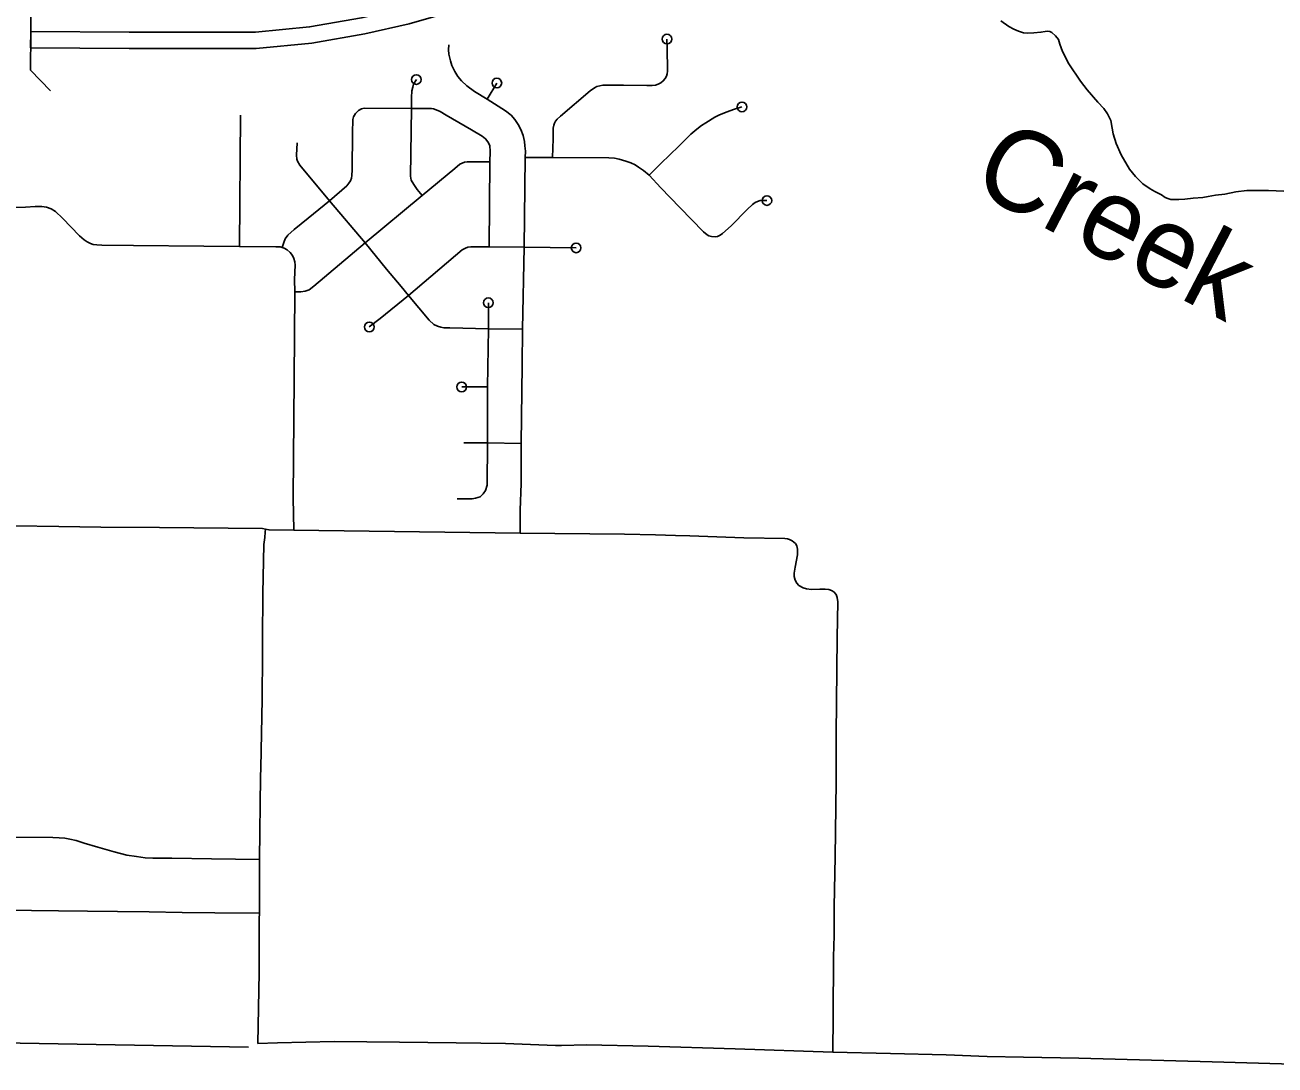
# Model space of a CAD drawing. Extents: x 670147 to 673275, y 705573 to 707613.
# Drawn here: x 671348.9 to 671478.7, y 706020.4 to 706128.4 of the extents above; entities that cross this region are included whole.
import ezdxf

# ---------------------------------------------------------------- set-up
doc = ezdxf.new("R2010")
doc.units = 0
for name, color, linetype in [('10', 7, 'Continuous'), ('2', 7, 'Continuous'), ('33', 7, 'Continuous'), ('34', 7, 'Continuous'), ('35', 7, 'Continuous'), ('39', 7, 'Continuous'), ('6', 7, 'Continuous')]:
    doc.layers.add(name, color=color, linetype=linetype)

msp = doc.modelspace()

# ---------------------------------------------------------------- linework, layer by layer
at = {"layer": '10'}
for points in [[(671431.65, 706153.97), (671430.6, 706155.28), (671422.59, 706148.88), (671415.95, 706143.47), (671412.2, 706140.79), (671407.79, 706137.98), (671403.85, 706135.95), (671399.39, 706133.87), (671393.5, 706131.61), (671388.41, 706130.14), (671383.89, 706129.13), (671378.49, 706128.18), (671372.87, 706127.64), (671359.76, 706127.63), (671349.56, 706127.7), (671349.51, 706126.02)], [(671349.51, 706126.02), (671359.76, 706125.95), (671372.95, 706125.96), (671378.71, 706126.51), (671384.22, 706127.48), (671388.83, 706128.51), (671394.04, 706130.01), (671400.05, 706132.32), (671404.59, 706134.44), (671408.63, 706136.52), (671413.14, 706139.39), (671416.97, 706142.13), (671423.65, 706147.57), (671431.65, 706153.97)]]:
    msp.add_lwpolyline(points, dxfattribs=at)
at = {"layer": '2'}
msp.add_lwpolyline([(671372.15, 706022.28), (671346.48, 706022.71), (671304.46, 706023.34), (671302.39, 706023.6)], dxfattribs=at)
at = {"layer": '33'}
for points in [[(671415.64, 706126.06), (671415.6, 706126.92)], [(671400.35, 706075.64), (671400.35, 706078.01), (671400.45, 706080.79), (671400.45, 706084.95), (671400.58, 706093.07), (671400.61, 706096.81), (671400.77, 706105.33), (671400.88, 706114.64), (671400.9, 706115.3), (671400.86, 706115.85), (671400.81, 706116.3), (671400.68, 706116.92), (671400.43, 706117.52), (671400.15, 706118.05), (671399.81, 706118.56), (671399.41, 706119.01), (671398.85, 706119.49), (671398.07, 706119.97), (671396.94, 706120.7), (671395.63, 706121.48), (671394.81, 706122.07), (671394.25, 706122.59), (671393.89, 706123.05), (671393.57, 706123.56), (671393.26, 706124.17), (671393.12, 706124.65), (671392.95, 706125.34), (671392.91, 706125.79), (671392.95, 706126.32)], [(671403.73, 706114.62), (671403.78, 706116.57), (671403.8, 706117.67), (671403.84, 706117.97), (671403.93, 706118.19), (671404.03, 706118.39), (671404.21, 706118.61), (671404.54, 706118.92), (671407.62, 706121.54), (671408.09, 706121.87), (671408.33, 706121.99), (671408.63, 706122.06), (671408.95, 706122.14), (671409.57, 706122.15), (671411.08, 706122.14), (671413.52, 706122.1), (671414.07, 706122.1), (671414.42, 706122.14), (671414.7, 706122.23), (671414.97, 706122.38), (671415.22, 706122.58), (671415.42, 706122.84), (671415.54, 706123.08), (671415.64, 706123.33), (671415.65, 706123.6), (671415.64, 706126.06), (671415.63, 706126.11)], [(671389.06, 706119.72), (671389.07, 706120.85), (671389.1, 706121.54), (671389.2, 706121.92), (671389.29, 706122.23), (671389.58, 706122.72)], [(671396.94, 706120.7), (671397.94, 706122.36)], [(671413.77, 706112.78), (671414.95, 706113.99), (671416.84, 706115.79), (671418.09, 706117.04), (671418.72, 706117.57), (671419.19, 706117.95), (671419.65, 706118.24), (671420.56, 706118.82), (671421.07, 706119.07), (671421.86, 706119.37), (671422.51, 706119.61), (671423.39, 706119.88)], [(671371.32, 706119.02), (671371.23, 706105.38)], [(671380.57, 706110.13), (671382.37, 706111.7), (671382.58, 706111.96), (671382.74, 706112.2), (671382.84, 706112.49), (671382.89, 706112.76), (671382.93, 706113.34), (671382.94, 706117.18), (671382.99, 706118.56), (671383.04, 706118.85), (671383.25, 706119.2), (671383.56, 706119.51), (671383.89, 706119.69), (671384.17, 706119.76), (671389.06, 706119.72), (671391.15, 706119.73), (671391.36, 706119.69), (671391.64, 706119.59), (671392.05, 706119.41), (671392.67, 706119.04), (671395.32, 706117.5), (671396.4, 706116.85), (671396.77, 706116.58), (671397, 706116.27), (671397.2, 706115.88), (671397.25, 706115.26), (671397.22, 706114.19), (671397.15, 706105.37)], [(671389.06, 706119.72), (671388.98, 706112.69), (671389.05, 706112.27), (671389.31, 706111.82), (671389.67, 706111.31), (671390.19, 706110.69)], [(671377.2, 706116.15), (671377.15, 706114.86), (671377.16, 706114.45), (671377.22, 706114.24), (671377.48, 706113.82), (671380.57, 706110.13), (671384.26, 706105.78), (671386.47, 706103.03), (671388.01, 706101.23), (671388.77, 706100.32), (671390.92, 706097.73), (671391.39, 706097.31), (671391.77, 706097.11), (671392.11, 706097), (671392.44, 706096.94), (671393.06, 706096.93), (671397.07, 706096.84), (671400.61, 706096.81)], [(671376.95, 706100.69), (671377.57, 706100.69), (671378.03, 706100.75), (671378.44, 706100.89), (671378.95, 706101.27), (671384.26, 706105.78), (671390.19, 706110.69), (671393.56, 706113.5), (671394.1, 706113.93), (671394.57, 706114.14), (671394.85, 706114.18), (671395.38, 706114.17), (671397.22, 706114.19)], [(671400.88, 706114.64), (671403.73, 706114.62), (671409.56, 706114.6), (671410.16, 706114.56), (671410.63, 706114.47), (671411.34, 706114.25), (671411.84, 706114.09), (671412.3, 706113.86), (671412.66, 706113.64), (671413.15, 706113.29), (671413.77, 706112.78), (671414.96, 706111.47), (671416.93, 706109.44), (671419.39, 706106.93), (671419.77, 706106.6), (671419.96, 706106.51), (671420.24, 706106.44), (671420.59, 706106.41), (671420.85, 706106.44), (671421.11, 706106.56), (671421.36, 706106.74), (671422.27, 706107.53), (671423.92, 706109.23), (671424.5, 706109.76), (671424.75, 706109.95), (671425.01, 706110.07), (671425.28, 706110.16), (671425.98, 706110.16)], [(671347.74, 706109.45), (671348.99, 706109.49), (671349.98, 706109.54), (671350.69, 706109.53), (671351.17, 706109.47), (671351.67, 706109.3), (671352.11, 706109.03), (671352.84, 706108.34), (671354.61, 706106.51), (671355.08, 706106.08), (671355.4, 706105.86), (671355.74, 706105.7), (671356.03, 706105.6), (671356.39, 706105.55), (671356.93, 706105.53), (671360.22, 706105.51), (671367.5, 706105.43), (671371.23, 706105.38)], [(671380.57, 706110.13), (671378.33, 706108.32), (671376.89, 706107.15), (671376.24, 706106.58), (671375.96, 706106.2), (671375.81, 706105.82), (671375.64, 706105.3)], [(671371.23, 706105.38), (671375, 706105.37), (671375.43, 706105.35), (671375.64, 706105.3), (671375.87, 706105.2), (671376.16, 706105.04), (671376.48, 706104.76), (671376.72, 706104.45), (671376.85, 706104.16), (671376.97, 706103.81), (671377, 706103.44), (671376.94, 706101.97), (671376.95, 706100.69), (671376.88, 706091.66), (671376.78, 706079.3), (671376.84, 706075.96)], [(671400.77, 706105.33), (671397.15, 706105.37), (671395.24, 706105.35), (671394.94, 706105.31), (671394.68, 706105.21), (671394.35, 706105.03), (671388.77, 706100.32)], [(671400.77, 706105.33), (671406.17, 706105.25)], [(671388.77, 706100.32), (671385.82, 706097.93)], [(671397.06, 706099.55), (671397.07, 706096.84)], [(671385.82, 706097.93), (671384.69, 706097.04)], [(671397.07, 706096.84), (671396.97, 706090.81), (671396.95, 706085), (671396.92, 706080.61), (671396.76, 706080.06), (671396.52, 706079.7), (671396.19, 706079.42), (671395.73, 706079.25), (671395.36, 706079.18), (671395, 706079.18), (671393.83, 706079.2)], [(671396.97, 706090.81), (671394.29, 706090.81)], [(671394.52, 706085.01), (671396.95, 706085), (671400.45, 706084.95)], [(671320.96, 706076.28), (671323.77, 706076.29), (671326.32, 706076.33), (671328.49, 706076.35), (671332.84, 706076.37), (671334.88, 706076.37), (671337.83, 706076.35), (671339.69, 706076.37), (671340.67, 706076.39), (671343.41, 706076.46), (671346.22, 706076.42), (671347.93, 706076.4), (671352.44, 706076.34), (671356.83, 706076.26), (671362.91, 706076.22), (671373.61, 706076.11)], [(671400.35, 706075.64), (671376.84, 706075.96), (671374.28, 706075.97), (671373.91, 706076.06), (671373.61, 706076.11)], [(671373.91, 706076.06), (671373.87, 706075.72), (671373.83, 706075.19), (671373.74, 706074.47), (671373.65, 706069.36), (671373.61, 706064.61)], [(671432.82, 706021.77), (671432.86, 706025.45), (671432.89, 706031.66), (671432.96, 706033.87), (671432.96, 706036.87), (671433.06, 706042.02), (671433.18, 706049.82), (671433.17, 706054.72), (671433.26, 706064.8), (671433.33, 706068.49), (671433.28, 706068.94), (671433.18, 706069.27), (671432.94, 706069.53), (671432.69, 706069.69), (671432.42, 706069.78), (671432.02, 706069.81), (671431.47, 706069.83), (671430.6, 706069.79), (671430.1, 706069.84), (671429.76, 706069.94), (671429.31, 706070.21), (671429.08, 706070.45), (671428.93, 706070.75), (671428.81, 706071.12), (671428.81, 706071.47), (671428.93, 706072.1), (671429.16, 706073.39), (671429.16, 706073.96), (671429.08, 706074.3), (671428.94, 706074.55), (671428.62, 706074.82), (671428.34, 706074.97), (671428.11, 706075.05), (671427.84, 706075.08), (671423.58, 706075.13), (671417.97, 706075.36), (671416.49, 706075.4), (671414.4, 706075.45), (671411.2, 706075.52), (671400.35, 706075.64)], [(671373.61, 706064.61), (671373.6, 706063.02), (671373.58, 706058.39), (671373.43, 706051.27), (671373.4, 706050.33), (671373.3, 706041.76), (671373.25, 706030.02), (671373.13, 706022.66)], [(671373.3, 706041.76), (671368.31, 706041.82), (671364.18, 706041.89), (671362.2, 706041.89), (671361.41, 706041.93), (671360.53, 706042.06), (671359.53, 706042.21), (671358.19, 706042.54), (671356.49, 706043.05), (671355.1, 706043.45), (671354.25, 706043.72), (671353.58, 706043.86), (671353.09, 706043.96), (671352.5, 706044.02), (671351.82, 706044.04), (671347.37, 706044.08)]]:
    msp.add_lwpolyline(points, dxfattribs=at)
for centre in [(671415.6, 706126.92), (671389.58, 706122.72), (671397.94, 706122.36), (671423.39, 706119.88), (671425.98, 706110.16), (671406.17, 706105.25), (671397.06, 706099.55), (671384.69, 706097.04), (671394.29, 706090.81)]:
    msp.add_circle(centre, 0.5, dxfattribs=at)
at = {"layer": '34'}
for points in [[(671432.82, 706021.77), (671422.67, 706022.11), (671413.65, 706022.39), (671407.24, 706022.5), (671404.64, 706022.46), (671404.03, 706022.46), (671398.84, 706022.64), (671393.7, 706022.71), (671387.83, 706022.79), (671381.06, 706022.86), (671375.15, 706022.73), (671373.13, 706022.66)], [(671432.82, 706021.77), (671438.82, 706021.61), (671444.58, 706021.49), (671448.84, 706021.32), (671452.62, 706021.22), (671458.38, 706021.12), (671472.21, 706020.75), (671479.41, 706020.56), (671485.51, 706020.42)]]:
    msp.add_lwpolyline(points, dxfattribs=at)
at = {"layer": '35'}
for points in [[(671450.28, 706128.83), (671451.11, 706128.23), (671451.61, 706127.94), (671452.11, 706127.73), (671452.61, 706127.57), (671453.04, 706127.54), (671453.71, 706127.57), (671454.44, 706127.64), (671454.88, 706127.72), (671455.15, 706127.73), (671455.36, 706127.72), (671455.56, 706127.62), (671455.96, 706127.27), (671456.27, 706126.87), (671456.39, 706126.4), (671456.68, 706125.65), (671457.33, 706124.35), (671458.53, 706122.56), (671459.23, 706121.65), (671460.33, 706120.39), (671460.98, 706119.72), (671461.35, 706119.17), (671461.68, 706118.47), (671461.82, 706117.66), (671461.95, 706117.08), (671462.26, 706116.08), (671462.76, 706114.92), (671463.63, 706113.43), (671464.27, 706112.66)], [(671464.27, 706112.66), (671465, 706111.89), (671465.77, 706111.36), (671466.27, 706111.11), (671466.95, 706110.76), (671467.33, 706110.49), (671467.62, 706110.36), (671467.93, 706110.28), (671468.3, 706110.28), (671468.74, 706110.26), (671469.38, 706110.3), (671470.23, 706110.42), (671471.24, 706110.48), (671471.8, 706110.59), (671472.57, 706110.71), (671473.52, 706110.82), (671474.68, 706111.07), (671475.82, 706111.19), (671478.07, 706111.21), (671479.65, 706111.15)]]:
    msp.add_lwpolyline(points, dxfattribs=at)
at = {"layer": '39'}
msp.add_line((671349.6, 706134.26), (671349.5, 706123.7), dxfattribs=at)
msp.add_lwpolyline([(671349.5, 706123.7), (671351.6, 706121.56)], dxfattribs=at)
at = {"layer": '6'}
msp.add_lwpolyline([(671346.74, 706023.37), (671346.84, 706030.62), (671346.92, 706036.5), (671349.63, 706036.47), (671352.43, 706036.43), (671355.43, 706036.4), (671358.53, 706036.36), (671361.83, 706036.32), (671365.25, 706036.27), (671368.66, 706036.23), (671373.28, 706036.18)], dxfattribs=at)

# ---------------------------------------------------------------- texts
at = {"layer": '35'}
msp.add_text('Creek', height=8.448, rotation=332.4871, dxfattribs=at).set_placement((671446.93, 706111.42))

doc.saveas('drawing.dxf')
